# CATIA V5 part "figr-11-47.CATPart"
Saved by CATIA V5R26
Part number: Part1
Bounding box of the stored display mesh (mm): x -171.181 to 0, y -220 to 0, z -11.432 to 46.691
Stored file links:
  D:\_Deepak\CATIA\CATIA V5-6R2016_Deepak\Resources\Part files\Partfiles\c11_catia_v5_6r2016_prt\figr-11-47.CATPart
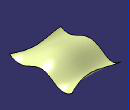
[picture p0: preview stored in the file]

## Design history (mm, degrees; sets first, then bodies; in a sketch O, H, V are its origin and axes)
Set1
  Sweep1: type Unspec, Profile Sketch2, Guide Sketch1
Body1 (main body)
  Sketch1 on yz-plane, origin (0, 0, 0), H (0, 1, 0), V (0, 0, 1)
    spline S1 through (0, 0) (-40, -10) (-100, 20) (-170, 0) (-220, 10)
    point P1 (0, 0)
    coincidence: P1 O
  Sketch2 on zx-plane, origin (0, 0, 0), H (-1, 0, 0), V (0, 0, 1)
    spline S1 through (0, 0) (60, 30) (121.1814, 19.9844) (171.1814, 9.9844)
    point P1 (0, 0)
    coincidence: P1 O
